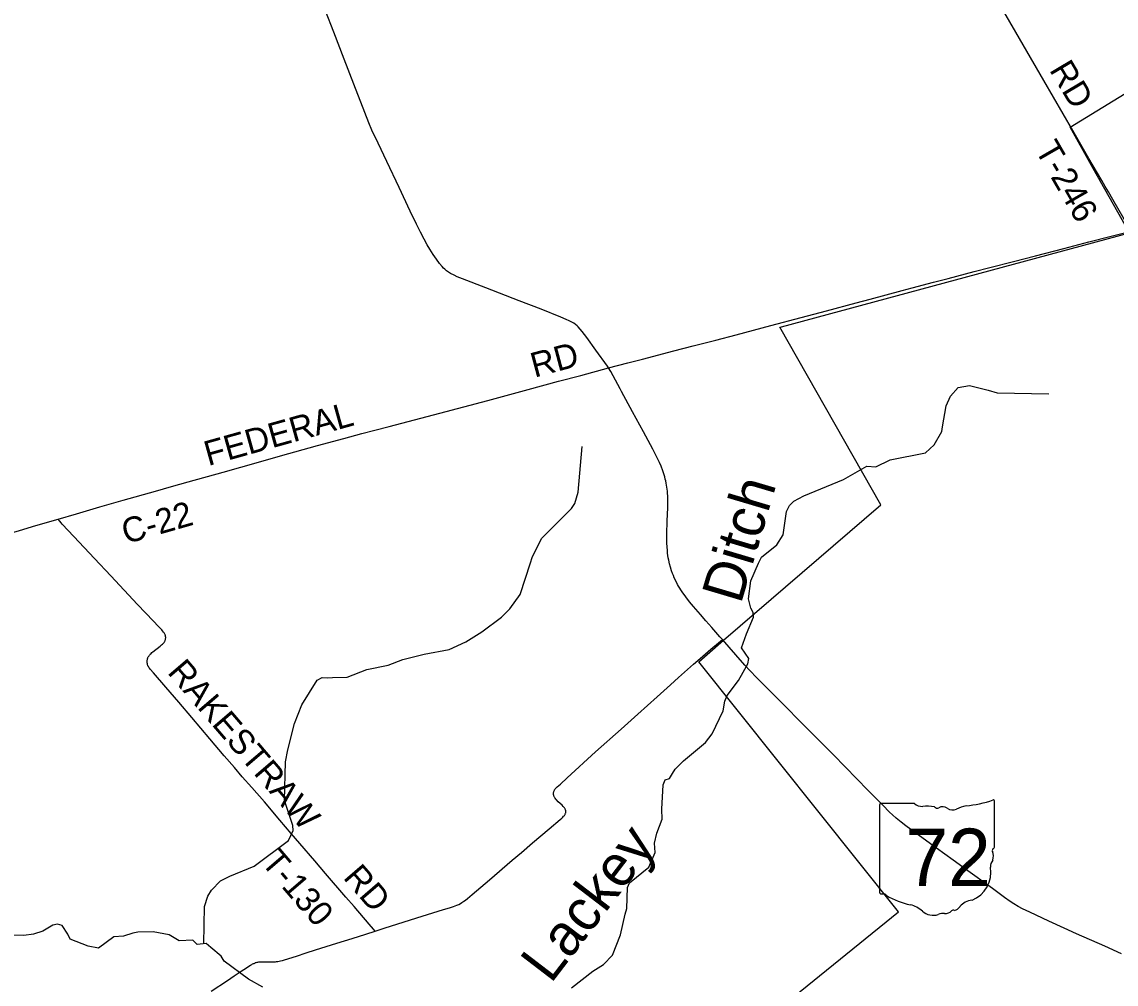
# Model space of a CAD drawing. Extents: x -49 to -8.2, y 9.4 to 23.5.
# Drawn here: x -14.04 to -12.785, y 14.037 to 15.141 of the extents above; entities that cross this region are included whole.
import ezdxf

# ---------------------------------------------------------------- set-up
doc = ezdxf.new("R2010")
doc.units = 0
for name, color, linetype in [('GM_X_County_Road', 7, 'Continuous'), ('GM_X_County_Road_Text', 7, 'Continuous'), ('GM_X_Minor_River', 7, 'Continuous'), ('GM_X_Minor_River_Text', 7, 'Continuous'), ('GM_X_State_Route', 7, 'Continuous'), ('GM_X_State_Shield', 7, 'Continuous'), ('GM_X_Township', 7, 'Continuous'), ('GM_X_Township_Road', 7, 'Continuous'), ('GM_X_Township_Road_Text', 7, 'Continuous')]:
    doc.layers.add(name, color=color, linetype=linetype)

msp = doc.modelspace()

# ---------------------------------------------------------------- linework, layer by layer
at = {"layer": 'GM_X_County_Road'}
for points in [[(-13.019, 14.8359), (-12.9946, 14.8424), (-12.9777, 14.8468), (-12.9477, 14.8547), (-12.93, 14.8595), (-12.9029, 14.8664), (-12.8776, 14.8729), (-12.845, 14.8813), (-12.8163, 14.8888), (-12.7907, 14.8953), (-12.7708, 14.9005), (-12.7678, 14.9012)], [(-13.3672, 14.7444), (-13.345, 14.7501), (-13.3283, 14.7544), (-13.2925, 14.7638), (-13.2703, 14.7696), (-13.2444, 14.7762), (-13.2209, 14.7822), (-13.1812, 14.7928), (-13.1462, 14.8021), (-13.1171, 14.8098), (-13.0832, 14.8187), (-13.067, 14.823), (-13.0303, 14.8329), (-13.019, 14.8359)], [(-13.9989, 14.5708), (-13.9777, 14.577), (-13.9508, 14.5848), (-13.9242, 14.5924), (-13.8871, 14.6029), (-13.8689, 14.608), (-13.8495, 14.6135), (-13.8094, 14.6248), (-13.769, 14.6361), (-13.7436, 14.6432), (-13.7011, 14.6551), (-13.6711, 14.6633), (-13.6504, 14.6689), (-13.6355, 14.6727), (-13.6188, 14.677), (-13.5608, 14.6922), (-13.5059, 14.7069), (-13.4807, 14.7137), (-13.4597, 14.7194), (-13.4246, 14.7289), (-13.3991, 14.7357), (-13.3672, 14.7444)], [(-14.2899, 14.488), (-14.2671, 14.4944), (-14.245, 14.5005), (-14.1989, 14.5133), (-14.1659, 14.5224), (-14.142, 14.529), (-14.0993, 14.5412), (-14.076, 14.5481), (-14.043, 14.5579), (-14.0245, 14.5634), (-13.9989, 14.5708)]]:
    msp.add_lwpolyline(points, dxfattribs=at)
at = {"layer": 'GM_X_Minor_River'}
for points in [[(-13.2065, 14.4108), (-13.2147, 14.4233), (-13.2089, 14.4391), (-13.201, 14.4583), (-13.2013, 14.4635), (-13.2041, 14.4686), (-13.2068, 14.4795), (-13.2042, 14.4998), (-13.1954, 14.5203), (-13.1918, 14.5271), (-13.1744, 14.5411), (-13.167, 14.5529), (-13.1632, 14.5796), (-13.1596, 14.5864), (-13.1548, 14.5914), (-13.1432, 14.5973), (-13.0979, 14.6164), (-13.071, 14.6316), (-13.0606, 14.6308), (-13.0441, 14.6389), (-13.0036, 14.6469), (-12.9936, 14.6558), (-12.9851, 14.6714), (-12.984, 14.6767), (-12.9801, 14.7008), (-12.975, 14.7117), (-12.9661, 14.7216), (-12.9532, 14.7239), (-12.9318, 14.7188), (-12.9216, 14.7158), (-12.8621, 14.7144)], [(-13.8315, 14.0837), (-13.8307, 14.1266), (-13.8271, 14.1381), (-13.823, 14.145), (-13.8126, 14.1559), (-13.8019, 14.1612), (-13.774, 14.1726), (-13.7345, 14.202), (-13.729, 14.2137), (-13.7295, 14.2194), (-13.7389, 14.248), (-13.7381, 14.2922), (-13.7354, 14.3062), (-13.7277, 14.3363), (-13.7191, 14.3576), (-13.7017, 14.386), (-13.6958, 14.389), (-13.6898, 14.3889), (-13.6839, 14.389), (-13.667, 14.3895), (-13.6447, 14.3982), (-13.6203, 14.4032), (-13.6032, 14.4096), (-13.5788, 14.416), (-13.5503, 14.4211), (-13.531, 14.4299), (-13.5128, 14.4416), (-13.4902, 14.4582), (-13.4804, 14.4679), (-13.4687, 14.4842), (-13.457, 14.5205), (-13.455, 14.5267), (-13.4441, 14.5486), (-13.4098, 14.5828), (-13.4061, 14.5888), (-13.4023, 14.6018), (-13.3975, 14.6539)], [(-13.4097, 14.0332), (-13.3853, 14.0522), (-13.373, 14.06), (-13.3628, 14.0707), (-13.3536, 14.0939), (-13.3483, 14.1176), (-13.3465, 14.124), (-13.3455, 14.1481), (-13.3432, 14.1534), (-13.3211, 14.1716), (-13.314, 14.1882), (-13.3146, 14.1991), (-13.312, 14.2104), (-13.3056, 14.2266), (-13.306, 14.2382), (-13.3047, 14.2659), (-13.3023, 14.2716), (-13.2975, 14.2734), (-13.2938, 14.2791), (-13.2907, 14.2839), (-13.2815, 14.2937), (-13.256, 14.3144), (-13.2486, 14.3245), (-13.2357, 14.3509), (-13.234, 14.362), (-13.2312, 14.3686), (-13.2183, 14.3855), (-13.2074, 14.4049), (-13.2065, 14.4108)], [(-13.764, 14.0338), (-13.7804, 14.043), (-13.8081, 14.0639), (-13.8118, 14.0695), (-13.8236, 14.0794), (-13.8289, 14.084), (-13.8393, 14.083), (-13.8443, 14.0877), (-13.8599, 14.0871), (-13.8712, 14.0938), (-13.8899, 14.0975), (-13.9072, 14.0971), (-13.913, 14.0959), (-13.9237, 14.0923), (-13.9347, 14.0915), (-13.9524, 14.0788), (-13.9643, 14.0809), (-13.985, 14.089), (-13.9878, 14.0946), (-13.9943, 14.1045), (-13.9995, 14.106), (-14.0049, 14.1051), (-14.0165, 14.098), (-14.0272, 14.0946), (-14.0382, 14.0932), (-14.0672, 14.0935)]]:
    msp.add_lwpolyline(points, dxfattribs=at)
at = {"layer": 'GM_X_State_Route'}
for points in [[(-13.3541, 14.7203), (-13.3648, 14.7402), (-13.3672, 14.7444), (-13.3685, 14.7462), (-13.3817, 14.7646), (-13.3923, 14.7791), (-13.3974, 14.7859), (-13.3998, 14.7888), (-13.4021, 14.7913), (-13.4033, 14.7925), (-13.4051, 14.794), (-13.4072, 14.7956), (-13.4094, 14.7968), (-13.4124, 14.7984), (-13.4158, 14.7999), (-13.4219, 14.8025), (-13.4447, 14.8115), (-13.4699, 14.8212), (-13.5079, 14.8359), (-13.5348, 14.8464), (-13.5409, 14.8488), (-13.5445, 14.8505), (-13.5486, 14.8526), (-13.551, 14.8541), (-13.5532, 14.8557), (-13.555, 14.8573), (-13.5566, 14.8588), (-13.5583, 14.8606), (-13.5612, 14.8641), (-13.5647, 14.8689), (-13.5686, 14.8745), (-13.5724, 14.8805), (-13.5753, 14.8853), (-13.579, 14.8918), (-13.5832, 14.8998), (-13.5878, 14.9092), (-13.5949, 14.9241), (-13.6077, 14.951), (-13.6218, 14.9808), (-13.6317, 15.0019), (-13.6387, 15.0171), (-13.6422, 15.0254), (-13.6469, 15.0372), (-13.6595, 15.0697), (-13.6707, 15.0983), (-13.6826, 15.1294), (-13.6922, 15.154)], [(-13.2555, 14.4541), (-13.2619, 14.4613), (-13.2699, 14.4705), (-13.2744, 14.476), (-13.2788, 14.4816), (-13.283, 14.4874), (-13.2845, 14.4896), (-13.2857, 14.4915), (-13.287, 14.4938), (-13.2881, 14.4958), (-13.2905, 14.5008), (-13.2919, 14.5036), (-13.2928, 14.506), (-13.2939, 14.5085), (-13.2949, 14.5114), (-13.2963, 14.5155), (-13.2974, 14.5194), (-13.2983, 14.5236), (-13.2988, 14.5263), (-13.2993, 14.5291), (-13.2996, 14.5316), (-13.2998, 14.5343), (-13.3002, 14.5395), (-13.3004, 14.5427), (-13.3004, 14.5457), (-13.3004, 14.5538), (-13.2999, 14.5684), (-13.2993, 14.5842), (-13.2992, 14.5914), (-13.2993, 14.5947), (-13.2993, 14.5972), (-13.2996, 14.6004), (-13.2998, 14.6029), (-13.3004, 14.6076), (-13.3012, 14.6122), (-13.3017, 14.6146), (-13.3022, 14.6167), (-13.3028, 14.6191), (-13.3035, 14.6216), (-13.3051, 14.6263), (-13.3071, 14.6316), (-13.3088, 14.6356), (-13.3125, 14.6434), (-13.3164, 14.6509), (-13.3272, 14.6708), (-13.3397, 14.6937), (-13.3524, 14.7172), (-13.3541, 14.7203)], [(-12.7787, 14.0723), (-12.7981, 14.0809), (-12.8305, 14.0951), (-12.8447, 14.1015), (-12.8621, 14.1095), (-12.8838, 14.1198), (-12.8924, 14.1239), (-12.8974, 14.1265), (-12.9022, 14.1294), (-12.9066, 14.1322), (-12.9132, 14.1369), (-12.927, 14.1469), (-12.9577, 14.1691), (-12.965, 14.1745), (-12.9718, 14.1794), (-12.9912, 14.1934), (-13.0148, 14.2105), (-13.0263, 14.219), (-13.0317, 14.2231), (-13.0372, 14.2277), (-13.0416, 14.2316), (-13.045, 14.2348), (-13.0526, 14.2425), (-13.0675, 14.2576), (-13.0847, 14.275), (-13.0936, 14.2842), (-13.1117, 14.3025), (-13.1444, 14.3357), (-13.1676, 14.3591), (-13.1834, 14.3749), (-13.197, 14.3886), (-13.2054, 14.3972), (-13.2109, 14.4032), (-13.2214, 14.415), (-13.2367, 14.4326), (-13.2396, 14.4359), (-13.2488, 14.4464), (-13.2555, 14.4541)]]:
    msp.add_lwpolyline(points, dxfattribs=at)
at = {"layer": 'GM_X_State_Shield'}
for p, q in [((-13.0563, 14.2428), (-13.0563, 14.1427)), ((-13.0164, 14.2445), (-13.055, 14.2445)), ((-12.9245, 14.1946), (-12.9245, 14.247)), ((-12.9245, 14.1946), (-12.9245, 14.1946))]:
    msp.add_line(p, q, dxfattribs=at)
for centre, radius, start, end in [((-12.9715, 14.3809), 0.1398, 275.8445, 288.9065), ((-12.926, 14.2472), 0.00147, 351.8621, 97.738), ((-13.0548, 14.243), 0.00153, 98.1301, 188.1301), ((-13.0072, 14.2561), 0.0148, 231.6195, 271.1119), ((-13.0023, 14.1883), 0.0532, 80.4867, 94.9883), ((-12.9902, 14.2435), 0.00427, 219.7921, 297.1024), ((-12.984, 14.2319), 0.00889, 54.4667, 119.1411), ((-12.9725, 14.2478), 0.0107, 233.8562, 294.8282), ((-12.9536, 14.2139), 0.0281, 97.3462, 120.7689), ((-12.9248, 14.1908), 0.00227, 107.944, 210.337), ((-12.9393, 14.1842), 0.0136, 340.033, 23.6496), ((-12.9261, 14.1944), 0.00157, 289.6038, 7.7341), ((-12.9192, 14.1727), 0.00992, 136.8065, 186.9296), ((-12.9636, 14.1661), 0.035, 292.3089, 8.9858), ((-13.0548, 14.1425), 0.00154, 171.9584, 258.3066), ((-13.0546, 14.1527), 0.0118, 267.339, 280.6039), ((-13.0522, 14.1369), 0.00424, 29.7484, 93.2717), ((-12.9986, 14.2268), 0.101, 240.4129, 257.1985), ((-13.0287, 14.0978), 0.0316, 47.1842, 75.836), ((-12.9731, 14.133), 0.0113, 282.8732, 323.2771), ((-12.9489, 14.1146), 0.0192, 94.4031, 142.5768), ((-12.9946, 14.1364), 0.02, 230.7004, 286.2918), ((-12.983, 14.1019), 0.0165, 85.6951, 111.2099), ((-12.9815, 14.129), 0.0107, 268.777, 315.5493), ((-12.9719, 14.1193), 0.00301, 65.7517, 132.6484)]:
    msp.add_arc(centre, radius, start, end, dxfattribs=at)
at = {"layer": 'GM_X_Township'}
msp.add_lwpolyline([(-13.3794, 13.8413), (-13.0346, 14.1202), (-13.2637, 14.4071), (-13.2542, 14.4154), (-13.2353, 14.4319), (-13.0551, 14.5871), (-13.1708, 14.7909), (-13.169, 14.7914), (-12.7695, 14.8992), (-12.8112, 14.973), (-12.8378, 15.0202), (-12.6759, 15.1194)], dxfattribs=at)
at = {"layer": 'GM_X_Township_Road'}
for points in [[(-12.7975, 14.9524), (-12.8015, 14.9593), (-12.8161, 14.9846), (-12.8347, 15.0165), (-12.868, 15.074), (-12.9152, 15.1556), (-13.005, 15.3111), (-13.0197, 15.3367), (-13.026, 15.3478), (-13.0275, 15.3503)], [(-12.7678, 14.9012), (-12.7691, 14.9034), (-12.7757, 14.915), (-12.7888, 14.9375), (-12.7938, 14.9461), (-12.7975, 14.9524)], [(-13.6352, 14.0982), (-13.637, 14.1003), (-13.642, 14.1063), (-13.6592, 14.1263), (-13.6688, 14.1373), (-13.6921, 14.1644), (-13.7044, 14.1788), (-13.7214, 14.1986), (-13.7313, 14.2102), (-13.7443, 14.2256), (-13.7622, 14.2463), (-13.7767, 14.263), (-13.7875, 14.2753), (-13.7965, 14.2857), (-13.8081, 14.2994), (-13.8246, 14.3188), (-13.8453, 14.3432), (-13.8603, 14.3607), (-13.8753, 14.3781), (-13.8893, 14.3944), (-13.8932, 14.3988), (-13.894, 14.3999), (-13.8946, 14.4007), (-13.8952, 14.4016), (-13.8955, 14.4021), (-13.8957, 14.4025), (-13.8959, 14.403), (-13.8961, 14.4035), (-13.8962, 14.404), (-13.8963, 14.4045), (-13.8964, 14.405), (-13.8965, 14.4056), (-13.8966, 14.4063), (-13.8966, 14.407), (-13.8966, 14.4077), (-13.8966, 14.4084), (-13.8965, 14.4091), (-13.8964, 14.4097), (-13.8963, 14.4102), (-13.8961, 14.4109), (-13.8959, 14.4114), (-13.8957, 14.412), (-13.8953, 14.4127), (-13.8949, 14.4134), (-13.8945, 14.414), (-13.8941, 14.4146), (-13.8936, 14.4152), (-13.8931, 14.4158), (-13.8921, 14.4168), (-13.8912, 14.4176), (-13.89, 14.4186), (-13.8819, 14.4249), (-13.88, 14.4265), (-13.879, 14.4274), (-13.8782, 14.4281), (-13.8776, 14.4288), (-13.8772, 14.4294), (-13.8769, 14.4299), (-13.8765, 14.4307), (-13.8761, 14.4313), (-13.8759, 14.432), (-13.8757, 14.4325), (-13.8756, 14.4332), (-13.8755, 14.4339), (-13.8754, 14.4346), (-13.8754, 14.4352), (-13.8755, 14.4359), (-13.8756, 14.4366), (-13.8757, 14.4371), (-13.8758, 14.4378), (-13.876, 14.4383), (-13.8763, 14.4389), (-13.8766, 14.4395), (-13.8771, 14.4403), (-13.8778, 14.4412), (-13.8789, 14.4426), (-13.8799, 14.4436), (-13.8813, 14.4452), (-13.8822, 14.4461), (-13.8839, 14.4479), (-13.8895, 14.4538), (-13.9077, 14.4729), (-13.9382, 14.5056), (-13.9569, 14.5256), (-13.9807, 14.551), (-13.994, 14.565), (-13.9954, 14.5666), (-13.9968, 14.5683), (-13.9989, 14.5708)], [(-13.2622, 14.4109), (-13.2499, 14.4215), (-13.239, 14.4308), (-13.2367, 14.4326)], [(-13.6352, 14.0982), (-13.6247, 14.1015), (-13.5874, 14.1134), (-13.5568, 14.1228), (-13.5497, 14.125), (-13.5452, 14.1264), (-13.5432, 14.1272), (-13.5412, 14.128), (-13.5392, 14.1289), (-13.5373, 14.1299), (-13.5355, 14.131), (-13.5334, 14.1324), (-13.5316, 14.1337), (-13.5291, 14.1356), (-13.5236, 14.1401), (-13.504, 14.157), (-13.4779, 14.1795), (-13.4673, 14.1885), (-13.4545, 14.1993), (-13.4356, 14.2155), (-13.4227, 14.2263), (-13.4208, 14.2279), (-13.4199, 14.2288), (-13.4188, 14.2299), (-13.4183, 14.2304), (-13.4179, 14.2309), (-13.4175, 14.2316), (-13.4172, 14.2321), (-13.4169, 14.2326), (-13.4166, 14.2333), (-13.4164, 14.2338), (-13.4163, 14.2344), (-13.4162, 14.2349), (-13.4162, 14.2354), (-13.4163, 14.236), (-13.4163, 14.2365), (-13.4165, 14.2369), (-13.4167, 14.2374), (-13.4169, 14.238), (-13.4172, 14.2385), (-13.4175, 14.239), (-13.4179, 14.2395), (-13.4186, 14.2403), (-13.4192, 14.241), (-13.4207, 14.2425), (-13.425, 14.2466), (-13.427, 14.2486), (-13.4278, 14.2495), (-13.4285, 14.2505), (-13.4289, 14.2511), (-13.4293, 14.2517), (-13.4296, 14.2523), (-13.4299, 14.2529), (-13.4301, 14.2535), (-13.4302, 14.254), (-13.4304, 14.2546), (-13.4304, 14.2554), (-13.4304, 14.256), (-13.4304, 14.2567), (-13.4304, 14.2572), (-13.4302, 14.2578), (-13.4301, 14.2584), (-13.4298, 14.259), (-13.4294, 14.2598), (-13.4292, 14.2602), (-13.4289, 14.2606), (-13.4284, 14.2613), (-13.428, 14.2618), (-13.4274, 14.2625), (-13.4268, 14.2632), (-13.4261, 14.2638), (-13.4226, 14.2669), (-13.4149, 14.2739), (-13.3821, 14.3037), (-13.353, 14.3299), (-13.3338, 14.3472), (-13.3116, 14.3671), (-13.2964, 14.3808), (-13.2871, 14.3891), (-13.2699, 14.4043), (-13.2622, 14.4109)], [(-13.8231, 14.0294), (-13.8044, 14.0417), (-13.7967, 14.0469), (-13.7887, 14.0522), (-13.7856, 14.0543), (-13.784, 14.0553), (-13.7812, 14.0572), (-13.778, 14.0592), (-13.7767, 14.0599), (-13.7756, 14.0605), (-13.7747, 14.0609), (-13.774, 14.0612), (-13.7732, 14.0616), (-13.7722, 14.062), (-13.7714, 14.0623), (-13.7704, 14.0625), (-13.7696, 14.0627), (-13.7686, 14.0628), (-13.7675, 14.063), (-13.7663, 14.063), (-13.7629, 14.0631), (-13.7564, 14.063), (-13.7527, 14.0629), (-13.7511, 14.0629), (-13.7493, 14.0631), (-13.7481, 14.0632), (-13.7467, 14.0633), (-13.7451, 14.0636), (-13.7435, 14.064), (-13.7413, 14.0645), (-13.7389, 14.0652), (-13.7253, 14.0695), (-13.7144, 14.0731), (-13.7034, 14.0766), (-13.6789, 14.0845), (-13.6614, 14.0899), (-13.6457, 14.0948), (-13.6352, 14.0982)]]:
    msp.add_lwpolyline(points, dxfattribs=at)

# ---------------------------------------------------------------- texts
at = {"layer": 'GM_X_County_Road_Text'}
for s, rotation, p in [('RD', 14.9946, (-13.4523, 14.7329)), ('FEDERAL', 15.5892, (-13.8266, 14.6316)), ('C-22', 15.9477, (-13.9211, 14.542))]:
    msp.add_text(s, height=0.02841, rotation=rotation, dxfattribs=at).set_placement(p)
at = {"layer": 'GM_X_Minor_River_Text'}
for s, height, rotation, p in [('Ditch', 0.04734, 73.4736, (-13.2156, 14.4723)), ('Lackey', 0.04736, 52.5718, (-13.4335, 14.037))]:
    msp.add_text(s, height=height, rotation=rotation, dxfattribs=at).set_placement(p)
at = {"layer": 'GM_X_State_Shield'}
msp.add_text('72', height=0.06592, dxfattribs=at).set_placement((-13.0268, 14.1498))
at = {"layer": 'GM_X_Township_Road_Text'}
for s, rotation, p in [('RD', 300.7174, (-12.8622, 15.0861)), ('T-246', 299.9216, (-12.8786, 14.9946)), ('RAKESTRAW', 310.5892, (-13.8743, 14.3946)), ('T-130', 310.6308, (-13.7669, 14.1766)), ('RD', 310.8141, (-13.6727, 14.1592))]:
    msp.add_text(s, height=0.02841, rotation=rotation, dxfattribs=at).set_placement(p)

doc.saveas('drawing.dxf')
